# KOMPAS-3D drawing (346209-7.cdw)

Referenced files: С1-3.cdw
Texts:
  КП.ОКМЧЕП.МЕ.12-01.000СП
  Текст на чертеже
  Размерные надписи
  Шероховатость
  Линия-выноска #1
  Линия-выноска #2
  Линия-выноска #3
  Отклонения формы и база
  Заголовок таблицы
  Ячейка таблицы
  Стрелка вида
  Обозначение изменения
  Фигурная скобка
  Номер узла
  Марка координационной оси
  VRCB
  Выносная надпись
  Обозначение узла
  Марка/позиционное обозначение с линией-выноской
  Марка/позиционное обозначение на линии
  Марка/позиционное обозначение без линии-выноски
  ТУ 38-101413-78
  Мастило ЦИАТИМ-201
  КП.ОКМЧЕП.МЕ.11.01.000СП-
  ГОСТ 6267-74
Dimensions and other numbers on the sheet: 7; 4; 1:1; 1; 0; 2; 3; 5; 6; 8; 9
